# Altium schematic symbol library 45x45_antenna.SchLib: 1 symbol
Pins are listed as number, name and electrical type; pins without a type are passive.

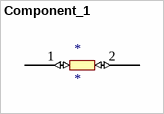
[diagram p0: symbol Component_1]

## Component_1
designator *
footprint PCBComponent_1
pins: 1 ANT1 (io), 2 ANT2 (io)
